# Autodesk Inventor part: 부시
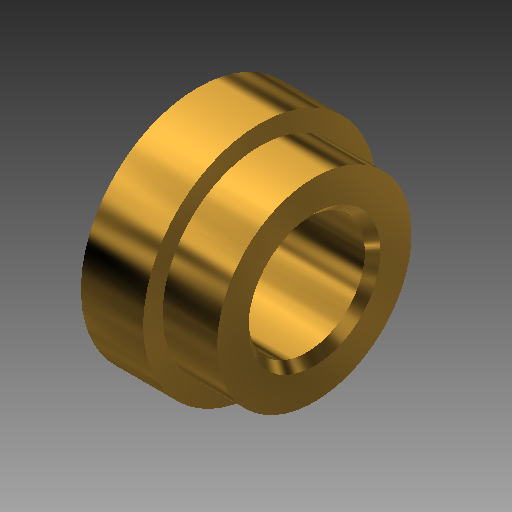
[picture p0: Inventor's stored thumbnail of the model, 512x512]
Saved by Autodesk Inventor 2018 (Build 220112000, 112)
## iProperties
Created: 2011-04
Part Number: 부시
Document SubType Name: Modeling
Density: 1 g/cm^3
Material: 일반
Appearance: 황동 - 새틴
Author: pww
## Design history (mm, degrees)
sketch "스케치1"
  geometry: L1 (0, 0)-(15, 0); L2 (0, 7.5)-(15, 7.5); L3 (15, 7.5)-(15, 12.5); L4 (15, 12.5)-(8, 12.5); L5 (8, 12.5)-(8, 15); L6 (8, 15)-(0, 15); L7 (0, 15)-(0, 7.5)
  constraints: 14 end point, 4 parallel, 2 vertical alignment, 1 horizontal, 1 perpendicular, 1 vertical
  dimensions: "d0" = 15 distance of L1.start L1.end; "d1" = 15 diameter of L2 L1; "d2" = 25 diameter of L4 L1; "d3" = 8 distance of L5.end L6.end; "d4" = 30 diameter of L6 L1
revolve "회전1" sketch "스케치1" stored, may be unused: angle "d5" = 90 deg
chamfer "모따기1" distance "d6" = 1; stored, may be unused: second distance "d7" = 2, angle "d8" = 45 deg
node "솔리드1"
